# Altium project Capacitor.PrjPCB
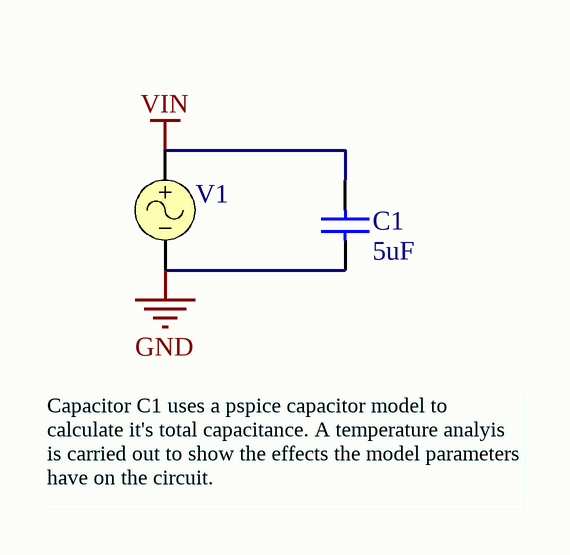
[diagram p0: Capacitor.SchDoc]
1 sheet, 2 parts. Net scope: global (net labels, ports and power ports of the same name join across sheets).

## Sheet Capacitor.SchDoc: Capacitor
size A; DocumentNumber: 1; SheetNumber: 1; SheetTotal: 1

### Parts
C1  value 5uF  [RAD-0.3]  (hidden comment: Cap)
V1  VSIN  (value not drawn)

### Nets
GND: C1.2 V1.2
VIN: C1.1 V1.1

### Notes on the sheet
- Capacitor C1 uses a pspice capacitor model to calculate it's total capacitance. A temperature analyis is carried out to show the effects the model parameters have on the circuit.

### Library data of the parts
C1 = Cap: Capacitor
V1 = VSIN: Sinusoidal Voltage Source; Note: PCB Footprint - Not required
